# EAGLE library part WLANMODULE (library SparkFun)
DPAC WiFi Module Footprint for DPAC wireless module. Not fully tested so double check it. Spark Fun Electronics SKU : (Module) RF-DPAC-Module, (Connector) RF-DPAC-Module-Con
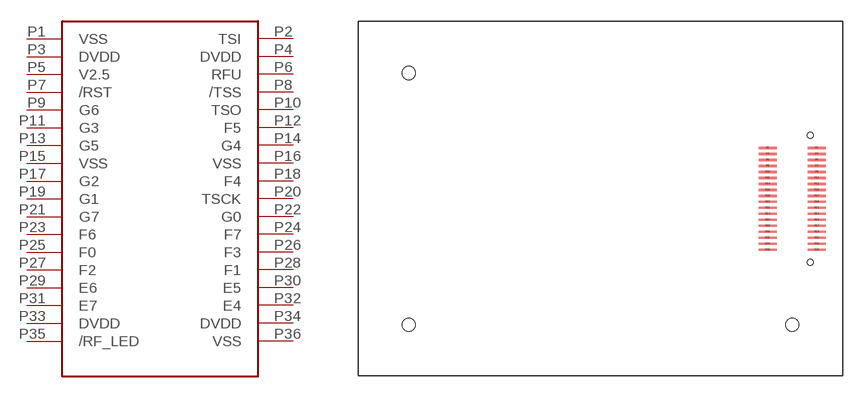
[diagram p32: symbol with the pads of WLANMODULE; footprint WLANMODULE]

Designator prefix -

## WLANMODULE  [WLANMODULE]
P1  VSS
P2  TSI
P3  DVDD
P4  DVDD
P5  V2.5
P6  RFU
P7  /RST
P8  /TSS
P9  G6
P10  TSO
P11  G3
P12  F5
P13  G5
P14  G4
P15  VSS
P16  VSS
P17  G2
P18  F4
P19  G1
P20  TSCK
P21  G7
P22  G0
P23  F6
P24  F7
P25  F0
P26  F3
P27  F2
P28  F1
P29  E6
P30  E5
P31  E7
P32  E4
P33  DVDD
P34  DVDD
P35  /RF_LED
P36  VSS

## Footprint WLANMODULE (pad centres in mm)
smd 1.5 x 0.2: P1 4.1,0; P2 0,0; P3 4.1,-0.5; P4 0,-0.5; P5 4.1,-1; P6 0,-1; P7 4.1,-1.5; P8 0,-1.5; P9 4.1,-2; P10 0,-2; P11 4.1,-2.5; P12 0,-2.5; P13 4.1,-3; P14 0,-3; P15 4.1,-3.5; P16 0,-3.5; P17 4.1,-4; P18 0,-4; P19 4.1,-4.5; P20 0,-4.5; P21 4.1,-5; P22 0,-5; P23 4.1,-5.5; P24 0,-5.5; P25 4.1,-6; P26 0,-6; P27 4.1,-6.5; P28 0,-6.5; P29 4.1,-7; P30 0,-7; P31 4.1,-7.5; P32 0,-7.5; P33 4.1,-8; P34 0,-8; P35 4.1,-8.5; P36 0,-8.5
hole 0.5 at 3.55,1.05
hole 0.5 at 3.54,-9.55
hole 1.1 at 2.05,-14.75
hole 1.1 at -29.95,-14.75
hole 1.1 at -29.95,6.25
